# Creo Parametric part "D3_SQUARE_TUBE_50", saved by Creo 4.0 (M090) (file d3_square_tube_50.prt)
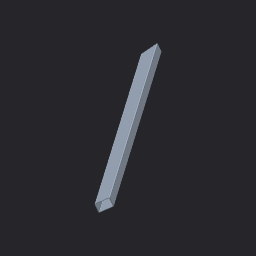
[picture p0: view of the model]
Units: Custom; MM, KILOGRAM, SECS
Materials in the file: STEEL

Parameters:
  BUW_NAME = "SQUARE TUBE"
  BUW_TYPE = "DIN EN 10210"
  BUW_SIZE = "60x60x3.0"
  BUW_LENGTH_STR = "847.3"
  PTC_MATERIAL_NAME = "STEEL"
  BUW_PROFIL_TYPE = "square_tube"
  BUW_PROFILE_PATH = "parts/profiles/steel_beams_mm/"
  BUW_PROFILE_NAME_LANG = "SQUARE TUBE"
  BUW_TAB_SEL_INFO = "2  0 2  3 19"
  MITRE_SYM_X_S = "|"
  MITRE_SYM_X_E = "|"
  MITRE_SYM_X = "|---|"
  MITRE_SYM_Y_S = "\"
  MITRE_SYM_Y_E = "\"
  MITRE_SYM_Y = "\---\"
  MITRE_BOM_Y = "Y \---\"
  BUW_DOUBLE_TO_STR_INFO = "X_ROT_S2 2 X_ROT_E2 2 Y_ROT_S2 2 Y_ROT_E2 2"
  X_ROT_S2_STR = "90"
  X_ROT_E2_STR = "90"
  Y_ROT_S2_STR = "45"
  Y_ROT_E2_STR = "60"
  BOM_ANGLE_S = "Y 45°"
  BOM_ANGLE_E = "Y 60°"
  EFX_ITEM_NR = "3"
  PROFIL_RASTER_POS = "X_0"
  BUW_OBJECT_ROLE = "PROFIL_SYSTEM_BORE_END_POINTS"
  PRO_UNIT_SYS = "Custom"

Other parameters: BUW_LENGTH, X_ROT_S2, X_ROT_E2, Y_ROT_S2, Y_ROT_E2, D8, D93, D94, d26, d8, d93, d94, d98, D98, D0, D4, D1, D5, SHEAR_MODULUS, THERM_EXPANSION_REF_TEMPERATURE, STRUCTURAL_DAMPING_COEFFICIENT, STRESS_LIMIT_FOR_TENSION, STRESS_LIMIT_FOR_COMPRESSION, STRESS_LIMIT_FOR_SHEAR, EMISSIVITY

Created from: SQUARE_TUBE.PRT

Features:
  1. datum plane "YZ"
  2. datum plane "XZ"
  3. datum plane "XY"
  4. coordinate system
  5. coordinate system
  6. coordinate system
  7. coordinate system
  8. datum plane "DTM3"
  9. datum plane "DTM4"
  10. datum plane "DTM5"
  11. protrusion
  12. round
  13. round
  14. datum axis
  15. datum point "PNT0"
  16. datum point

Other named items: PROFIL_CUT_QUILT, PROFILE_LENGTH_DIM, CONTACT_SURF_3, CONTACT_SURF_2, CONTACT_SURF_1, CONTACT_SURF_0, E, START_SURFACE, END_SURFACE, SIDE_SURF_3, SIDE_SURF_0, SIDE_SURF_1, SIDE_SURF_2, EDGE_7_S, EDGE_7_E, EDGE_1_S, EDGE_1_E, EDGE_3_S, EDGE_3_E, EDGE_5_S, EDGE_5_E, EDGE_6_S, EDGE_4_S, EDGE_2_S, EDGE_0_S, EDGE_6_E, EDGE_4_E, EDGE_2_E, EDGE_0_E, CS0, CS_S, CS_E, CS3

Named dimensions: X_ROT_S, Y_ROT_S, Z_OFF_S, X_ROT_E, Y_ROT_E, Z_OFF_E, PC_L, BUW_LENGTH_Z_MIN, BUW_LENGTH_DIM

Layers: .WHITE_HOLE, 00_PROFIL_DATUM, 00_PROFIL_DRW_HIDE, 00_PROFIL_END_CSYS, 00_PROFIL_GEOMETRY, 00_PROFIL_QUILT, 00_PROFIL_SIZE_NOTE

Surfaces: 10 plane, 8 cylinder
